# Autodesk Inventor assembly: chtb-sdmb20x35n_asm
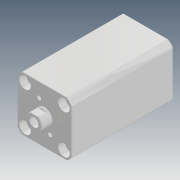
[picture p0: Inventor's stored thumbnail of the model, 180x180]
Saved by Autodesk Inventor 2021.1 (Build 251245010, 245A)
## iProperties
Company: Microsoft
Created: 2018-05
Part Number: chtb-sdmb20x35n_asm
Description: STEP AP214
Document SubType Name: Assembly
Designer: user
Title: chtb-sdmb20x35n_asm.STEP
Author: Windows
Revision Number: ÈÎºÎ
Sending System: SolidWorks 2015
Preprocessor: SwSTEP 2.0
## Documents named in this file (4)
- D:\Vault_2016\Projekty\Clamptek\Hydraulic\CHTB\CHTB-20\Inventor\CHTB-SDMB20x35N\chtb-sdmb20x35n_asm.iam
- D:\Vault_2016\Projekty\Clamptek\Hydraulic\CHTB\CHTB-20\Inventor\CHTB-SDMB20x35N\CHTB-SDMB20X35NBT.ipt
- D:\Vault_2016\Projekty\Clamptek\Hydraulic\CHTB\CHTB-20\Inventor\CHTB-SDMB20x35N\CHTB-SDMB20X35NHSG.ipt
- D:\Vault_2016\Projekty\Clamptek\Hydraulic\CHTB\CHTB-20\Inventor\CHTB-SDMB20x35N\QG_3.ipt
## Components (3 placed, 3 different names)
1. CHTB-SDMB20X35NBT_1
2. CHTB-SDMB20X35NHSG_2
3. QG_3_3
